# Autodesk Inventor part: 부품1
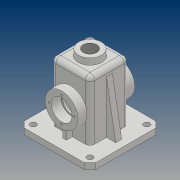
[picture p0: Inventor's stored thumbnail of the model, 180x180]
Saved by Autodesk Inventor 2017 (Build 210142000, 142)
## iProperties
Part Number: 부품1
Material: 일반
Document SubType Name: Modeling
Designer: 20
Density: 1 g/cm^3
Appearance: 기본값
Author: 20
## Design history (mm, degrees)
sketch "스케치1"
  geometry: L1 (-32.5, 32.5)-(32.5, 32.5); L2 (32.5, 32.5)-(32.5, -32.5); L3 (32.5, -32.5)-(-32.5, -32.5); L4 (-32.5, -32.5)-(-32.5, 32.5); L5 (-32.5, 32.5)-(32.5, -32.5); L6 (32.5, 32.5)-(-32.5, -32.5); 1 further point
  constraints: 12 end point, 2 midpoint, 2 parallel, 1 horizontal, 1 perpendicular
  dimensions: "d0" = 65 distance of L2.end L3.end; "d1" = 65 distance of L1.end L2.end
extrude "돌출1" new body sketch "스케치1" distance "d2" = 100; taper "d3" = 0 deg
fillet "모깎기1" dims "d4" = 8
fillet "모깎기2" dims "d5" = 8
feature "쉘1" dims "d8" = 5
sketch "스케치3"
  geometry: L1 (-60, -60)-(60, -60); L2 (60, -60)-(60, 60); L3 (60, 60)-(-60, 60); L4 (-60, 60)-(-60, -60); L5 (-60, -60)-(60, 60); L6 (60, -60)-(-60, 60); L7 (-27.5, -24.5)-(-27.5, 24.5) reference; L8 (27.5, 24.5)-(27.5, -24.5) reference; L9 (-24.5, 27.5)-(24.5, 27.5) reference; L10 (24.5, -27.5)-(-24.5, -27.5) reference; A1 r 3 centre (24.5, -24.5) between (24.5, -27.5) and (27.5, -24.5) reference; A2 r 3 centre (24.5, 24.5) between (27.5, 24.5) and (24.5, 27.5) reference; A3 r 3 centre (-24.5, 24.5) between (-24.5, 27.5) and (-27.5, 24.5) reference; A4 r 3 centre (-24.5, -24.5) between (-27.5, -24.5) and (-24.5, -27.5) reference; 1 further point
  constraints: 12 end point, 2 midpoint, 2 parallel, 1 horizontal, 1 perpendicular
  dimensions: "d9" = 120 distance of L3.end L2.end; "d10" = 120 distance of L2.end L1.end
extrude "돌출2" join sketch "스케치3" distance "d11" = 10; taper "d12" = 0 deg
sketch "스케치4"
  geometry: C1 r 20 at (0, 0); 1 further point
  constraints: 1 centre point, 1 coincident
  dimensions: "d13" = 40 diameter of C1
extrude "돌출3" join sketch "스케치4" distance "d14" = 10; taper "d15" = -5 deg
hole "구멍1" diameter "d18" = 22.835; stored, may be unused: countersink angle "d22" = 90 deg, drill point angle "d24" = 0 deg; dims "d16" = 10, "d17" = 10, "d19" = 50, "d20" = 4, "d21" = 2, "d23" = 59.3
chamfer "모따기1" distance "d25" = 10; stored, may be unused: second distance "d26" = 2, angle "d27" = 45 deg
sketch "스케치5"
  geometry: L1 (74.5, -92)-(-25.5, -92) reference; L2 (74.5, -102)-(-25.5, -102) reference; C1 r 27.5 at (24.5, -47); 2 further points
  constraints: 1 centre point, 1 midpoint, 1 vertical alignment
  dimensions: "d28" = 55 diameter of C1; "d29" = 55 distance from line of L2 C1.centre
extrude "돌출4" join sketch "스케치5" distance "d30" = 15; taper "d31" = 0 deg
sketch "스케치6"
  geometry: C1 r 27.5 at (0, 0) reference; C2 r 17.5 at (0, 0); 1 further point
  constraints: 1 centre point, 1 coincident
  dimensions: "d32" = 35 diameter of C2
extrude "돌출5" cut sketch "스케치6" distance "d33" = 17; taper "d34" = 0 deg
sketch "스케치7"
  geometry: C1 r 17.5 at (0, 0) reference; C2 r 17.5 at (0, 0) reference; C3 r 15 at (0, 0); 1 further point
  constraints: 1 centre point, 1 coincident
  dimensions: "d35" = 30 diameter of C3
extrude "돌출6" cut sketch "스케치7" distance "d36" = 3; taper "d37" = 0 deg
sketch "스케치8"
  geometry: L1 (60, 50)-(60, -50) reference; L2 (50, -60)-(-50, -60) reference; C1 r 5 at (47.5, -47.5); 1 further point
  constraints: 1 centre point
  dimensions: "d38" = 10 diameter of C1; "d39" = 12.5 distance from line of L1 C1.centre; "d40" = 12.5 distance from line of L2 C1.centre
extrude "돌출7" cut sketch "스케치8" stored distance "d41" = 3; taper "d42" = 0 deg
sketch "스케치9"
  geometry: L1 (-50, 0)-(-60, 0) reference; L2 (-48, 0)-(-36.539, 65); L3 (-60, 0)-(-60, -10) reference; 1 further point
  constraints: 2 end point, 1 point on line
  dimensions: "d49" = 12 distance from line of L3 L2.start; "d50" = 10 deg angle of L3 L2; "d51" = 65 vertical distance of L2.start L2.end
feature "리브1" sketch "스케치9" dims "d52" = 1, "d53" = 10, "d54" = 0, "d55" = 0, "d56" = 1, "d57" = 1
sketch "스케치11"
  geometry: L1 (-3, -27.5)-(3, -27.5); L2 (3, -27.5)-(3, -42.5); L3 (3, -42.5)-(-3, -42.5); L4 (-3, -42.5)-(-3, -27.5); L5 (50, -60)-(-50, -60) reference; L6 (-24.5, -27.5)-(24.5, -27.5) reference; 3 further points
  constraints: 8 end point, 2 midpoint, 2 parallel, 1 horizontal, 1 perpendicular, 1 point on line, 1 vertical alignment
  dimensions: "d58" = 6 distance of L2.end L3.end; "d59" = 15 distance of L1.end L2.end
extrude "돌출8" join sketch "스케치11" stored distance "d60" = 3; taper "d61" = 0 deg
sketch "스케치12"
  geometry: L1 (50, -45)-(-50, -45) reference; C1 r 15 at (0, 0) reference; 3 further points
  constraints: 1 midpoint, 1 vertical alignment
  dimensions: "d62" = 21 distance of C1.centre point (0, 21)
hole "구멍2" sketch "스케치12" at (0, 21) diameter "d63" = 3.242; stored, may be unused: countersink angle "d67" = 90 deg, drill point angle "d69" = 118 deg; dims "d64" = 8, "d65" = 4, "d66" = 2, "d68" = 10
fillet "모깎기3" dims "d73" = 0.3
node "솔리드1"
mirror "미러1"
pattern_linear "직사각형 패턴1" dims "d45" = 95, "d48" = 95
mirror "미러2"
mirror "미러3"
pattern_circular "원형 패턴1" dims angle "d71" = 360 deg
mirror "미러4"
node "작업 평면1"
